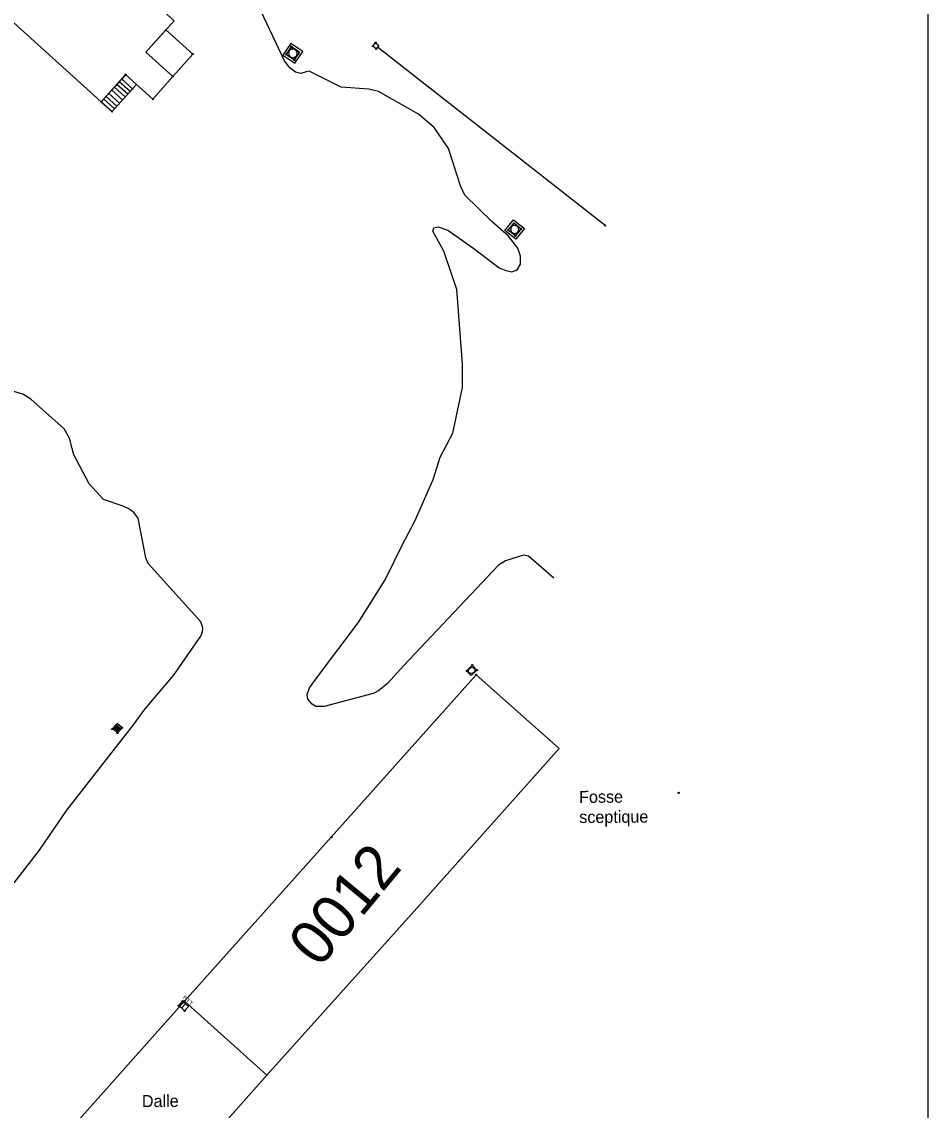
# Model space of a CAD drawing. Extents: x 344013 to 344423, y 298505 to 298795.
# Drawn here: x 344347.8 to 344422.9, y 298605.2 to 298695.5 of the extents above; entities that cross this region are included whole.
import ezdxf

# ---------------------------------------------------------------- set-up
doc = ezdxf.new("R2010")
doc.units = 0
for name, color, linetype in [('Default', 7, 'Continuous'), ('DH_CADRE -CARTOUCHE', 7, 'Continuous'), ('DH_CADRE-CARTOUCHE-NORD', 7, 'Continuous'), ('PC_CONCRETE', 7, 'Continuous'), ('PS_BOLT', 7, 'Continuous'), ('PS_CONST', 7, 'Continuous'), ('PS_DIM', 7, 'Continuous'), ('PS_HIDDEN', 7, 'Continuous'), ('PS_WELD', 7, 'Continuous'), ('TOPO_COURBE NIVEAU', 7, 'Continuous'), ('TOPO_POINT', 7, 'Continuous')]:
    doc.layers.add(name, color=color, linetype=linetype)

# ---------------------------------------------------------------- blocks, each defined once
blk = doc.blocks.new('R5')
at = {"layer": 'Default'}
for p, q in [((0, 1), (0, 0)), ((1, 1), (0, 1)), ((0, 0), (1, 0)), ((0.2, 1), (0.2, 0)), ((0.4, 1), (0.4, 0)), ((0.6, 1), (0.6, 0)), ((0.6, 0), (0.6, 0)), ((0.8, 1), (0.8, 0)), ((1, 0), (1, 1))]:
    blk.add_line(p, q, dxfattribs=at)
blk = doc.blocks.new('REG_INC')
at = {"layer": 'Default'}
for p, q in [((0, 1), (1, 1)), ((0, 0), (0, 1)), ((1, 0), (0, 0)), ((1, 1), (1, 0))]:
    blk.add_line(p, q, dxfattribs=at)
for start, end in [(135.0055, 180.0055), (180.0066, 225.0066), (90.0058, 135.0058), (225.0069, 270.0069), (45.0069, 90.0069), (270.0058, 315.0058), (0.0066, 45.0066), (315.0055, 0.0055)]:
    blk.add_arc((0.5, 0.5), 0.44, start, end, dxfattribs=at)
blk = doc.blocks.new('CT2')
at = {"layer": 'Default'}
blk.add_lwpolyline([(0, 0), (1, 0), (1, 1), (0, 1)], close=True, dxfattribs=at)
blk.add_lwpolyline([(0.5, 1), (0.5, 0)], dxfattribs=at)
blk.add_text('PTT', height=0.6, dxfattribs=at).set_placement((-0.3, 1.43))
blk = doc.blocks.new('POINT_DISPLAY')
at = {"layer": 'Default'}
blk.add_circle((0, 0), 0.05, dxfattribs=at)

msp = doc.modelspace()

# ---------------------------------------------------------------- linework, layer by layer
at = {"layer": 'DH_CADRE -CARTOUCHE'}
for points in [[(344012.906, 298504.876), (344422.906, 298504.876), (344422.906, 298791.876), (344012.906, 298791.876)], [(344300.695, 298736.911), (344309.284, 298729.159), (344318.375, 298721.074), (344331.766, 298709.041), (344345.307, 298697.002), (344354.351, 298688.866), (344356.37, 298691.11), (344358.623, 298689.083), (344360.288, 298690.966), (344358.051, 298692.978), (344360.392, 298695.581), (344306.859, 298743.741)], [(344377.142, 298693.244), (344376.865, 298693.48), (344377.093, 298693.758), (344377.37, 298693.522)], [(344361.238, 298614.297), (344368.087, 298608.155), (344380.276, 298621.746), (344392.299, 298635.233), (344385.431, 298641.355), (344373.418, 298627.878)]]:
    msp.add_lwpolyline(points, close=True, dxfattribs=at)
at = {"layer": 'PC_CONCRETE'}
msp.add_lwpolyline([(344370.111, 298693.428), (344369.678, 298692.782), (344370.352, 298692.328), (344370.785, 298692.974)], close=True, dxfattribs=at)
at = {"layer": 'PS_BOLT'}
for points in [[(344370.056, 298693.706), (344369.4, 298692.727), (344370.406, 298692.05), (344371.062, 298693.028)], [(344389.444, 298678.362), (344388.713, 298677.466), (344387.8, 298678.185), (344388.531, 298679.082)], [(344361.238, 298614.297), (344350.978, 298602.747), (344357.784, 298596.545), (344368.087, 298608.155)]]:
    msp.add_lwpolyline(points, close=True, dxfattribs=at)
msp.add_lwpolyline([(344360.288, 298690.966), (344358.051, 298692.978)], dxfattribs=at)
at = {"layer": 'PS_DIM'}
msp.add_lwpolyline([(344354.351, 298688.866), (344355.248, 298688.059), (344356.94, 298689.939), (344356.043, 298690.746)], close=True, dxfattribs=at)
for points in [[(344356.94, 298689.939), (344357.267, 298690.303), (344356.37, 298691.11), (344356.043, 298690.746)], [(344356.123, 298689.031), (344355.226, 298689.838)], [(344356.338, 298689.27), (344355.441, 298690.077)], [(344356.539, 298689.493), (344355.642, 298690.3)], [(344356.739, 298689.716), (344355.842, 298690.523)], [(344355.449, 298688.282), (344354.552, 298689.089)], [(344355.649, 298688.505), (344354.753, 298689.312)], [(344355.868, 298688.748), (344354.972, 298689.555)]]:
    msp.add_lwpolyline(points, dxfattribs=at)
at = {"layer": 'PS_HIDDEN'}
msp.add_lwpolyline([(344361.927, 298692.821), (344359.707, 298694.819), (344358.051, 298692.978), (344360.288, 298690.966)], close=True, dxfattribs=at)
at = {"layer": 'PS_WELD'}
msp.add_lwpolyline([(344396.125, 298678.61), (344377.256, 298693.383)], dxfattribs=at)
at = {"layer": 'TOPO_COURBE NIVEAU'}
for points in [[(344391.867, 298649.365), (344389.778, 298651.193), (344389.353, 298651.273), (344387.866, 298650.811), (344387.291, 298650.442), (344379.434, 298642.124), (344378.085, 298640.624), (344377.329, 298640.026), (344376.903, 298639.807), (344372.83, 298638.718), (344372.137, 298638.735), (344371.831, 298638.916), (344371.461, 298639.318), (344371.408, 298639.719), (344371.62, 298640.262), (344372.37, 298641.307), (344375.642, 298645.668), (344377.891, 298649.229), (344379.32, 298652.146), (344380.354, 298654.088), (344381.863, 298657.556), (344382.448, 298659.398), (344383.506, 298661.395), (344384.306, 298665.16), (344384.294, 298667.128), (344383.832, 298673.295), (344382.759, 298676.468), (344381.826, 298678.146), (344381.929, 298678.405), (344382.267, 298678.507), (344383.069, 298678.223), (344385.225, 298676.706), (344387.338, 298675.091), (344387.895, 298674.862), (344388.399, 298674.767), (344388.84, 298674.939), (344389.092, 298675.411), (344389.101, 298676.065), (344388.89, 298676.718), (344388.112, 298677.719), (344386.745, 298678.901), (344384.476, 298681.115), (344384.123, 298681.894), (344383.129, 298684.988), (344381.935, 298686.724), (344380.646, 298687.827), (344377.343, 298689.721), (344376.532, 298689.92), (344374.226, 298690.074), (344371.574, 298691.393), (344371.322, 298691.346), (344370.897, 298691.205), (344370.449, 298691.325), (344369.969, 298691.68), (344369.546, 298692.262), (344367.098, 298697.415)], [(344347.121, 298624.114), (344349.225, 298626.809), (344351.488, 298630.115), (344357.023, 298637.202), (344357.992, 298638.529), (344360.333, 298641.303), (344362.612, 298644.563), (344362.731, 298644.917), (344362.771, 298645.24), (344362.607, 298645.752), (344358.24, 298650.588), (344358.036, 298651.045), (344357.404, 298654.344), (344357.059, 298654.817), (344356.643, 298655.123), (344356.171, 298655.329), (344354.536, 298655.898), (344353.344, 298657.19), (344352.072, 298659.6), (344351.931, 298660.119), (344351.712, 298660.97), (344351.28, 298661.75), (344348.524, 298664.216), (344347.856, 298664.619), (344346.439, 298665.031)]]:
    msp.add_lwpolyline(points, dxfattribs=at)

# ---------------------------------------------------------------- block references
at = {"layer": 'DH_CADRE-CARTOUCHE-NORD', "xscale": 0.6549609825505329, "yscale": 0.48444481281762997, "rotation": -41.07076232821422}
msp.add_blockref('CT2', (344360.766, 298613.921), dxfattribs=at)
at = {"layer": 'PC_CONCRETE'}
for name, p, xscale, yscale, rotation in [('REG_INC', (344369.678, 298692.782), 0.812974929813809, 0.778206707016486, -33.97716000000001), ('REG_INC', (344388.683, 298677.744), 0.756702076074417, 0.7629925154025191, 50.803739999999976), ('REG_INC', (344385.11, 298642.144), 0.5553809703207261, -0.6636107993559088, -46.679220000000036), ('R5', (344355.699, 298636.524), 0.5763452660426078, 0.5584033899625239, 48.25539)]:
    msp.add_blockref(name, p, dxfattribs=dict(at, xscale=xscale, yscale=yscale, rotation=rotation))
at = {"layer": 'TOPO_POINT'}
for p in [(344370.111, 298693.428), (344376.865, 298693.48), (344377.093, 298693.758), (344361.927, 298692.821), (344369.678, 298692.782), (344377.142, 298693.244), (344370.352, 298692.328), (344356.37, 298691.11), (344360.288, 298690.966), (344356.94, 298689.939), (344358.623, 298689.083), (344354.351, 298688.866), (344355.248, 298688.059), (344388.083, 298678.217), (344389.161, 298678.331), (344396.125, 298678.61), (344388.683, 298677.744), (344385.11, 298642.144), (344384.65, 298641.665), (344385.431, 298641.355), (344385.491, 298641.74), (344355.247, 298636.857), (344356.083, 298636.954), (344355.699, 298636.524), (344402.22, 298631.569), (344373.418, 298627.878), (344361.085, 298614.286), (344361.238, 298614.297), (344360.766, 298613.921), (344361.263, 298613.491)]:
    msp.add_blockref('POINT_DISPLAY', p, dxfattribs=at)

# ---------------------------------------------------------------- texts
at = {"layer": 'PS_CONST'}
for s, height, rotation, p in [('Fosse', 1.0003, 0.36646, (344393.965, 298630.727)), ('sceptique', 1.0003, 0.36646, (344393.976, 298629.06)), ('0012', 3.662, 50.36649, (344372.425, 298616.956)), ('Dalle', 1.0003, 0.36648, (344357.721, 298605.504))]:
    msp.add_text(s, height=height, rotation=rotation, dxfattribs=at).set_placement(p)

doc.saveas('drawing.dxf')
